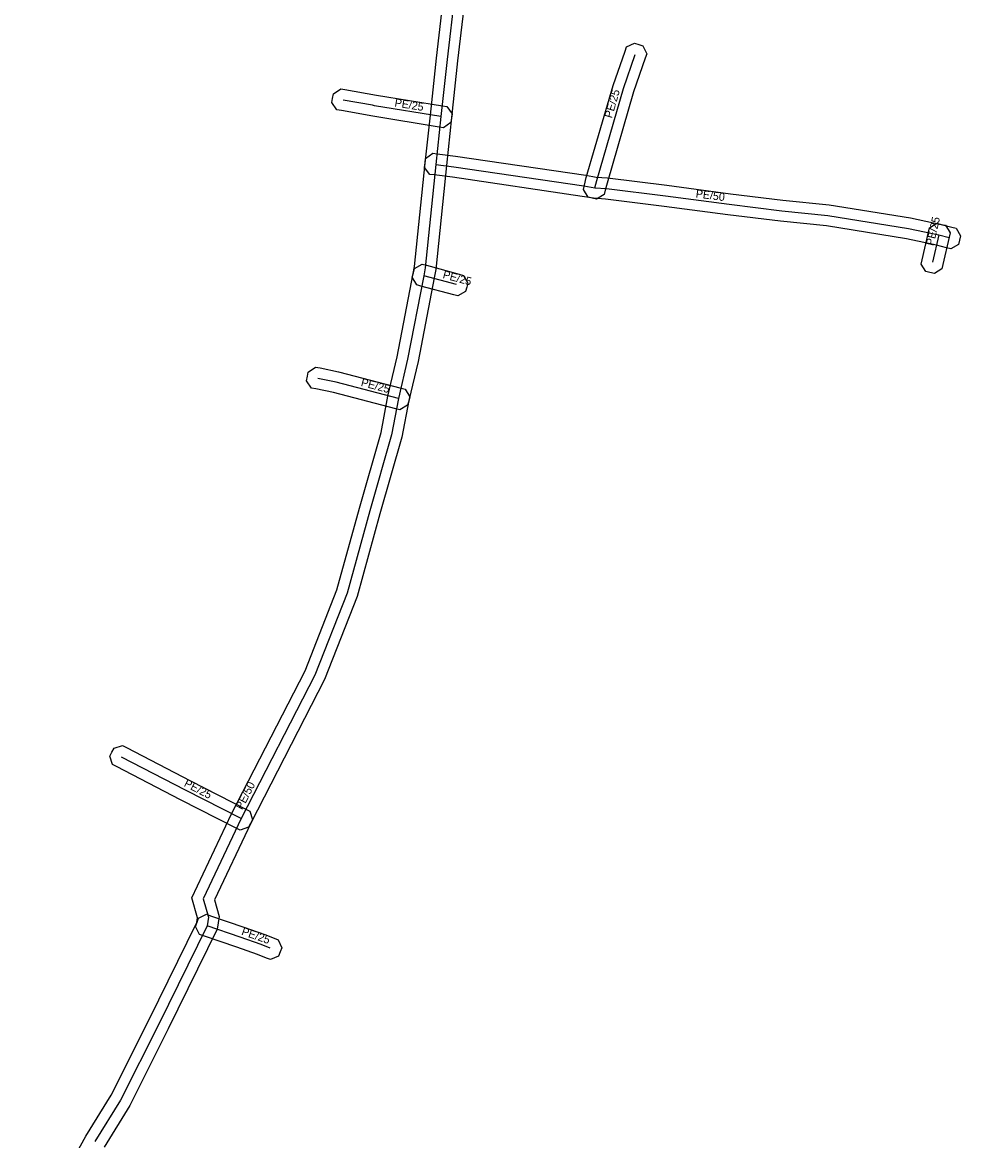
# Model space of a CAD drawing. Extents: x -681050 to -680828, y -1057939 to -1057551.
# Drawn here: x -680929 to -680841, y -1057745.3 to -1057640.5 of the extents above; entities that cross this region are included whole.
import ezdxf

# ---------------------------------------------------------------- set-up
doc = ezdxf.new("R2010")
doc.units = 0
for name, color, linetype in [('1', 7, 'Continuous'), ('24', 7, 'Continuous'), ('30', 7, 'Continuous')]:
    doc.layers.add(name, color=color, linetype=linetype)

msp = doc.modelspace()

# ---------------------------------------------------------------- linework, layer by layer
at = {"layer": '1'}
for points in [[(-680928.96, -1057755.66), (-680923.02, -1057744.92), (-680920.63, -1057741.05), (-680917.08, -1057733.96), (-680912.61, -1057724.87), (-680912.54, -1057724.43), (-680913.08, -1057722.58), (-680909.36, -1057714.7), (-680902.46, -1057701.29), (-680899.47, -1057693.7), (-680897.36, -1057686.04), (-680895.33, -1057678.95), (-680894.7, -1057675.55), (-680893.83, -1057671.87), (-680892.32, -1057664.07), (-680892.19, -1057663.39), (-680891.21, -1057653.73), (-680890.72, -1057649.23), (-680890.14, -1057643.89), (-680888.7, -1057631.45)], [(-680886.72, -1057631.77), (-680888.16, -1057644.11), (-680888.74, -1057649.45), (-680889.22, -1057653.93), (-680890.21, -1057663.69), (-680890.36, -1057664.45), (-680891.87, -1057672.29), (-680892.74, -1057675.97), (-680893.39, -1057679.41), (-680895.44, -1057686.58), (-680897.57, -1057694.34), (-680900.64, -1057702.11), (-680907.56, -1057715.58), (-680910.95, -1057722.76), (-680910.5, -1057724.31), (-680910.69, -1057725.49), (-680915.28, -1057734.84), (-680918.89, -1057742.03), (-680921.3, -1057745.93)]]:
    msp.add_lwpolyline(points, dxfattribs=at)
for points in [[(-680876.37, -1057656.18), (-680876.27, -1057655.78), (-680876.1, -1057655.07), (-680873.58, -1057646.43), (-680872.46, -1057643.21), (-680872.33, -1057642.82), (-680871.58, -1057642.46), (-680871.19, -1057642.6), (-680870.8, -1057642.73), (-680870.44, -1057643.48), (-680870.58, -1057643.87), (-680871.68, -1057647.03), (-680874.16, -1057655.59), (-680874.33, -1057656.26), (-680874.43, -1057656.66), (-680875.14, -1057657.09), (-680875.54, -1057656.99), (-680875.94, -1057656.89)], [(-680889.48, -1057650.39), (-680889.89, -1057650.33), (-680896.11, -1057649.32), (-680899.06, -1057648.79), (-680899.47, -1057648.72), (-680899.95, -1057648.04), (-680899.88, -1057647.64), (-680899.8, -1057647.23), (-680899.12, -1057646.75), (-680898.72, -1057646.82), (-680895.77, -1057647.34), (-680889.57, -1057648.35), (-680889.16, -1057648.42), (-680888.68, -1057649.09), (-680888.74, -1057649.5), (-680888.81, -1057649.91)], [(-680890.5, -1057652.78), (-680890.09, -1057652.84), (-680888.37, -1057653.06), (-680876.16, -1057654.85), (-680875.18, -1057655.03), (-680874.13, -1057655.09), (-680868.56, -1057655.79), (-680862.58, -1057656.58), (-680857.67, -1057657.18), (-680853.34, -1057657.62), (-680845.73, -1057658.85), (-680842.83, -1057659.45), (-680841.83, -1057659.71), (-680841.43, -1057659.82), (-680841.02, -1057660.54), (-680841.12, -1057660.94), (-680841.23, -1057661.34), (-680841.95, -1057661.75), (-680842.35, -1057661.65), (-680843.29, -1057661.39), (-680846.09, -1057660.81), (-680853.6, -1057659.6), (-680857.89, -1057659.16), (-680862.84, -1057658.56), (-680868.82, -1057657.77), (-680874.31, -1057657.09), (-680875.42, -1057657.01), (-680876.48, -1057656.83), (-680888.65, -1057655.04), (-680890.35, -1057654.82), (-680890.76, -1057654.77), (-680891.27, -1057654.11), (-680891.21, -1057653.7), (-680891.16, -1057653.29)], [(-680841.99, -1057660.24), (-680842.09, -1057660.65), (-680842.69, -1057663.22), (-680842.78, -1057663.62), (-680843.48, -1057664.06), (-680843.89, -1057663.96), (-680844.29, -1057663.87), (-680844.73, -1057663.17), (-680844.63, -1057662.76), (-680844.03, -1057660.19), (-680843.94, -1057659.79), (-680843.24, -1057659.35), (-680842.83, -1057659.45), (-680842.43, -1057659.54)], [(-680888.13, -1057666.16), (-680888.53, -1057666.05), (-680891.6, -1057665.23), (-680892, -1057665.12), (-680892.41, -1057664.4), (-680892.31, -1057664), (-680892.2, -1057663.6), (-680891.48, -1057663.19), (-680891.08, -1057663.29), (-680888.01, -1057664.12), (-680887.61, -1057664.23), (-680887.2, -1057664.95), (-680887.31, -1057665.35), (-680887.41, -1057665.75)], [(-680893.57, -1057676.83), (-680893.97, -1057676.73), (-680899.79, -1057675.21), (-680901.46, -1057674.87), (-680901.86, -1057674.79), (-680902.32, -1057674.1), (-680902.24, -1057673.69), (-680902.16, -1057673.29), (-680901.47, -1057672.83), (-680901.06, -1057672.91), (-680899.33, -1057673.26), (-680893.47, -1057674.79), (-680893.07, -1057674.9), (-680892.65, -1057675.61), (-680892.75, -1057676.01), (-680892.86, -1057676.41)], [(-680908.55, -1057716.22), (-680908.92, -1057716.03), (-680914.13, -1057713.37), (-680920.13, -1057710.26), (-680920.5, -1057710.07), (-680920.75, -1057709.28), (-680920.56, -1057708.91), (-680920.37, -1057708.54), (-680919.58, -1057708.29), (-680919.21, -1057708.48), (-680913.21, -1057711.59), (-680908.01, -1057714.25), (-680907.64, -1057714.44), (-680907.38, -1057715.23), (-680907.57, -1057715.59), (-680907.76, -1057715.96)], [(-680905.69, -1057728.36), (-680906.08, -1057728.21), (-680906.93, -1057727.89), (-680908.87, -1057727.2), (-680911.98, -1057726.12), (-680912.37, -1057725.99), (-680912.73, -1057725.24), (-680912.59, -1057724.85), (-680912.46, -1057724.46), (-680911.71, -1057724.1), (-680911.32, -1057724.24), (-680908.21, -1057725.32), (-680906.23, -1057726.01), (-680905.36, -1057726.35), (-680904.97, -1057726.5), (-680904.64, -1057727.25), (-680904.79, -1057727.64), (-680904.94, -1057728.02)]]:
    msp.add_lwpolyline(points, close=True, dxfattribs=at)
at = {"layer": '24'}
for points in [[(-680887.71, -1057631.61), (-680889.15, -1057644), (-680889.73, -1057649.34), (-680890.22, -1057653.83), (-680891.2, -1057663.54), (-680891.34, -1057664.26), (-680892.85, -1057672.08), (-680893.72, -1057675.76), (-680894.36, -1057679.18), (-680896.4, -1057686.31), (-680898.52, -1057694.02), (-680901.55, -1057701.7), (-680908.46, -1057715.14), (-680912.01, -1057722.67), (-680911.52, -1057724.37), (-680911.65, -1057725.18), (-680916.18, -1057734.4), (-680919.76, -1057741.54), (-680922.16, -1057745.42)], [(-680875.3, -1057656.02), (-680875.13, -1057655.33), (-680872.63, -1057646.73), (-680871.52, -1057643.54)], [(-680889.73, -1057649.34), (-680895.94, -1057648.33), (-680896.15, -1057648.29), (-680898.89, -1057647.81)], [(-680890.22, -1057653.83), (-680888.51, -1057654.05), (-680876.32, -1057655.84), (-680875.3, -1057656.02), (-680874.22, -1057656.09), (-680868.69, -1057656.78), (-680862.71, -1057657.57), (-680857.78, -1057658.17), (-680853.47, -1057658.61), (-680845.91, -1057659.83), (-680843.06, -1057660.42), (-680842.09, -1057660.68)], [(-680843.06, -1057660.42), (-680843.66, -1057662.99)], [(-680888.27, -1057665.09), (-680891.34, -1057664.26)], [(-680893.72, -1057675.76), (-680899.56, -1057674.23), (-680901.26, -1057673.89)], [(-680908.46, -1057715.14), (-680913.67, -1057712.48), (-680919.67, -1057709.37)], [(-680905.72, -1057727.28), (-680906.58, -1057726.95), (-680908.54, -1057726.26), (-680911.65, -1057725.18)]]:
    msp.add_lwpolyline(points, dxfattribs=at)

# ---------------------------------------------------------------- texts
at = {"layer": '30'}
for s, rotation, p in [('PE/25', 73.791, (-680873.71, -1057649.55)), ('PE/25', 350.7622, (-680894.11, -1057648.39)), ('PE/50', 352.4744, (-680865.88, -1057656.92)), ('PE/25', 76.8589, (-680843.56, -1057661.51)), ('PE/25', 344.8713, (-680889.61, -1057664.48)), ('PE/25', 345.3192, (-680897.28, -1057674.58)), ('PE/25', 332.6008, (-680913.87, -1057712.07)), ('PE/50', 62.7906, (-680908.36, -1057714.37)), ('PE/25', 340.8496, (-680908.48, -1057726.01))]:
    msp.add_text(s, height=0.75, rotation=rotation, dxfattribs=at).set_placement(p)

doc.saveas('drawing.dxf')
